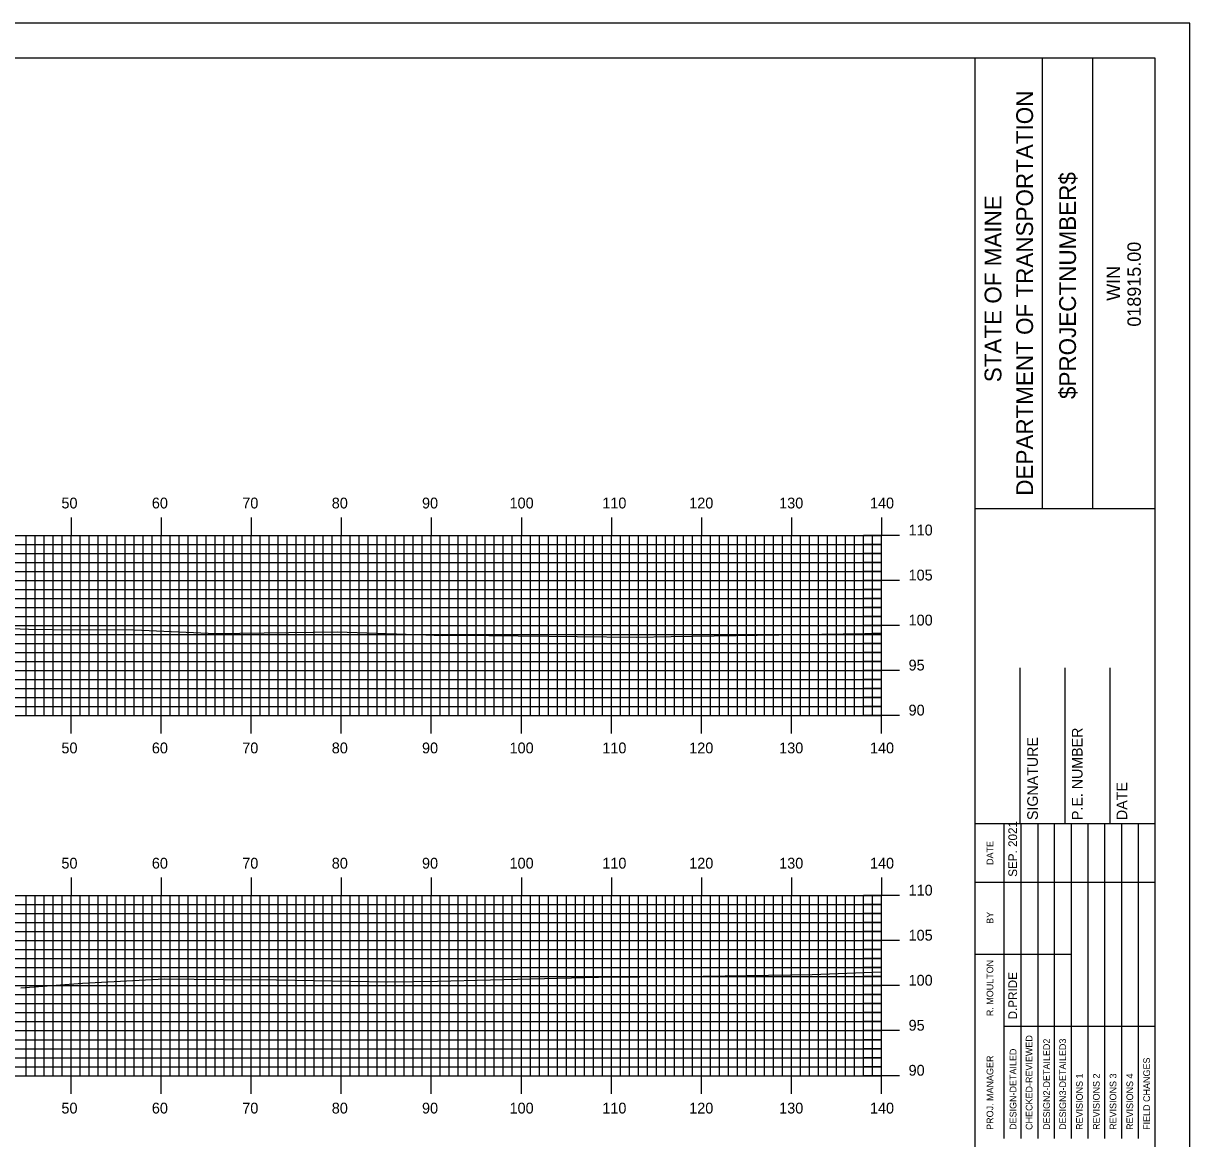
# Model space of a CAD drawing. Extents: x 1774383 to 1774727, y 442591 to 442811.
# Drawn here: x 1774593.9 to 1774723.4, y 442686.7 to 442810.5 of the extents above; entities that cross this region are included whole.
import ezdxf

# ---------------------------------------------------------------- set-up
doc = ezdxf.new("R2010")
doc.units = 0
for name, color, linetype in [('BORDER', 7, 'Continuous'), ('H_V ANNOTATION', 7, 'Continuous'), ('MAJOR', 7, 'Continuous'), ('MINOR', 7, 'Continuous'), ('PLOT BOUNDARY', 7, 'Continuous'), ('S_Roadway_Centerline', 7, 'Continuous')]:
    doc.layers.add(name, color=color, linetype=linetype)

msp = doc.modelspace()

# ---------------------------------------------------------------- linework, layer by layer
at = {"layer": 'BORDER'}
for p, q in [((1774699.57, 442596.67), (1774699.57, 442806.67)), ((1774707.03, 442756.66), (1774707.03, 442806.66)), ((1774712.62, 442756.66), (1774712.62, 442806.66)), ((1774699.57, 442756.65), (1774719.57, 442756.65)), ((1774704.57, 442721.67), (1774704.57, 442738.97)), ((1774709.57, 442721.67), (1774709.57, 442738.97)), ((1774714.57, 442721.67), (1774714.57, 442738.97)), ((1774699.57, 442721.67), (1774719.57, 442721.67))]:
    msp.add_line(p, q, dxfattribs=at)
msp.add_lwpolyline([(1774399.57, 442596.67), (1774719.57, 442596.67), (1774719.57, 442806.67), (1774399.57, 442806.67)], close=True, dxfattribs=at)
for points in [[(1774702.8, 442715.17), (1774702.8, 442721.67)], [(1774704.67, 442686.68), (1774704.67, 442721.67)], [(1774706.53, 442721.67), (1774706.53, 442686.68)], [(1774708.39, 442686.68), (1774708.39, 442721.67)], [(1774710.26, 442686.68), (1774710.26, 442721.67)], [(1774712.12, 442686.68), (1774712.12, 442721.67)], [(1774713.98, 442686.68), (1774713.98, 442721.67)], [(1774715.85, 442686.68), (1774715.85, 442721.67)], [(1774717.71, 442686.68), (1774717.71, 442721.67)], [(1774702.8, 442686.68), (1774702.8, 442720.26)], [(1774699.57, 442715.17), (1774719.57, 442715.17)], [(1774699.57, 442707.17), (1774702.8, 442707.17)], [(1774702.8, 442707.17), (1774710.26, 442707.17)], [(1774702.8, 442699.17), (1774719.57, 442699.17)]]:
    msp.add_lwpolyline(points, dxfattribs=at)
at = {"layer": 'MAJOR'}
for p, q in [((1774599.17, 442755.67), (1774599.17, 442753.67)), ((1774609.17, 442755.67), (1774609.17, 442753.67)), ((1774619.17, 442755.67), (1774619.17, 442753.67)), ((1774629.17, 442755.67), (1774629.17, 442753.67)), ((1774639.17, 442755.67), (1774639.17, 442753.67)), ((1774649.17, 442755.67), (1774649.17, 442753.67)), ((1774659.17, 442755.67), (1774659.17, 442753.67)), ((1774669.17, 442755.67), (1774669.17, 442753.67)), ((1774679.17, 442755.67), (1774679.17, 442753.67)), ((1774689.17, 442755.67), (1774689.17, 442753.67)), ((1774409.17, 442753.67), (1774689.17, 442753.67)), ((1774409.17, 442753.67), (1774689.17, 442753.67)), ((1774599.17, 442733.67), (1774599.17, 442753.67)), ((1774609.17, 442733.67), (1774609.17, 442753.67)), ((1774619.17, 442733.67), (1774619.17, 442753.67)), ((1774629.17, 442733.67), (1774629.17, 442753.67)), ((1774639.17, 442733.67), (1774639.17, 442753.67)), ((1774649.17, 442733.67), (1774649.17, 442753.67)), ((1774659.17, 442733.67), (1774659.17, 442753.67)), ((1774669.17, 442733.67), (1774669.17, 442753.67)), ((1774679.17, 442733.67), (1774679.17, 442753.67)), ((1774691.18, 442753.67), (1774687.17, 442753.67)), ((1774689.17, 442733.67), (1774689.17, 442753.67)), ((1774689.17, 442733.67), (1774689.17, 442753.67)), ((1774409.17, 442748.67), (1774689.17, 442748.67)), ((1774691.18, 442748.67), (1774687.17, 442748.67)), ((1774409.17, 442743.67), (1774689.17, 442743.67)), ((1774691.18, 442743.67), (1774687.17, 442743.67)), ((1774409.17, 442738.67), (1774689.17, 442738.67)), ((1774691.18, 442738.67), (1774687.17, 442738.67)), ((1774409.17, 442733.67), (1774689.17, 442733.67)), ((1774409.17, 442733.67), (1774689.17, 442733.67)), ((1774599.17, 442731.66), (1774599.17, 442733.67)), ((1774609.17, 442731.66), (1774609.17, 442733.67)), ((1774619.17, 442731.66), (1774619.17, 442733.67)), ((1774629.17, 442731.66), (1774629.17, 442733.67)), ((1774639.17, 442731.66), (1774639.17, 442733.67)), ((1774649.17, 442731.66), (1774649.17, 442733.67)), ((1774659.17, 442731.66), (1774659.17, 442733.67)), ((1774669.17, 442731.66), (1774669.17, 442733.67)), ((1774679.17, 442731.66), (1774679.17, 442733.67)), ((1774691.18, 442733.67), (1774687.17, 442733.67)), ((1774689.17, 442731.66), (1774689.17, 442733.67)), ((1774599.17, 442715.67), (1774599.17, 442713.67)), ((1774609.17, 442715.67), (1774609.17, 442713.67)), ((1774619.17, 442715.67), (1774619.17, 442713.67)), ((1774629.17, 442715.67), (1774629.17, 442713.67)), ((1774639.17, 442715.67), (1774639.17, 442713.67)), ((1774649.17, 442715.67), (1774649.17, 442713.67)), ((1774659.17, 442715.67), (1774659.17, 442713.67)), ((1774669.17, 442715.67), (1774669.17, 442713.67)), ((1774679.17, 442715.67), (1774679.17, 442713.67)), ((1774689.17, 442715.67), (1774689.17, 442713.67)), ((1774409.17, 442713.67), (1774689.17, 442713.67)), ((1774409.17, 442713.67), (1774689.17, 442713.67)), ((1774599.17, 442693.67), (1774599.17, 442713.67)), ((1774609.17, 442693.67), (1774609.17, 442713.67)), ((1774619.17, 442693.67), (1774619.17, 442713.67)), ((1774629.17, 442693.67), (1774629.17, 442713.67)), ((1774639.17, 442693.67), (1774639.17, 442713.67)), ((1774649.17, 442693.67), (1774649.17, 442713.67)), ((1774659.17, 442693.67), (1774659.17, 442713.67)), ((1774669.17, 442693.67), (1774669.17, 442713.67)), ((1774679.17, 442693.67), (1774679.17, 442713.67)), ((1774691.18, 442713.67), (1774687.17, 442713.67)), ((1774689.17, 442693.67), (1774689.17, 442713.67)), ((1774689.17, 442693.67), (1774689.17, 442713.67)), ((1774409.17, 442708.67), (1774689.17, 442708.67)), ((1774691.18, 442708.67), (1774687.17, 442708.67)), ((1774409.17, 442703.67), (1774689.17, 442703.67)), ((1774691.18, 442703.67), (1774687.17, 442703.67)), ((1774409.17, 442698.67), (1774689.17, 442698.67)), ((1774691.18, 442698.67), (1774687.17, 442698.67)), ((1774409.17, 442693.67), (1774689.17, 442693.67)), ((1774409.17, 442693.67), (1774689.17, 442693.67)), ((1774599.17, 442691.66), (1774599.17, 442693.67)), ((1774609.17, 442691.66), (1774609.17, 442693.67)), ((1774619.17, 442691.66), (1774619.17, 442693.67)), ((1774629.17, 442691.66), (1774629.17, 442693.67)), ((1774639.17, 442691.66), (1774639.17, 442693.67)), ((1774649.17, 442691.66), (1774649.17, 442693.67)), ((1774659.17, 442691.66), (1774659.17, 442693.67)), ((1774669.17, 442691.66), (1774669.17, 442693.67)), ((1774679.17, 442691.66), (1774679.17, 442693.67)), ((1774691.18, 442693.67), (1774687.17, 442693.67)), ((1774689.17, 442691.66), (1774689.17, 442693.67))]:
    msp.add_line(p, q, dxfattribs=at)
at = {"layer": 'MINOR'}
for p, q in [((1774594.17, 442733.67), (1774594.17, 442753.67)), ((1774595.17, 442733.67), (1774595.17, 442753.67)), ((1774596.17, 442733.67), (1774596.17, 442753.67)), ((1774597.17, 442733.67), (1774597.17, 442753.67)), ((1774598.17, 442733.67), (1774598.17, 442753.67)), ((1774600.17, 442733.67), (1774600.17, 442753.67)), ((1774601.17, 442733.67), (1774601.17, 442753.67)), ((1774602.17, 442733.67), (1774602.17, 442753.67)), ((1774603.17, 442733.67), (1774603.17, 442753.67)), ((1774604.17, 442733.67), (1774604.17, 442753.67)), ((1774605.17, 442733.67), (1774605.17, 442753.67)), ((1774606.17, 442733.67), (1774606.17, 442753.67)), ((1774607.17, 442733.67), (1774607.17, 442753.67)), ((1774608.17, 442733.67), (1774608.17, 442753.67)), ((1774610.17, 442733.67), (1774610.17, 442753.67)), ((1774611.17, 442733.67), (1774611.17, 442753.67)), ((1774612.17, 442733.67), (1774612.17, 442753.67)), ((1774613.17, 442733.67), (1774613.17, 442753.67)), ((1774614.17, 442733.67), (1774614.17, 442753.67)), ((1774615.17, 442733.67), (1774615.17, 442753.67)), ((1774616.17, 442733.67), (1774616.17, 442753.67)), ((1774617.17, 442733.67), (1774617.17, 442753.67)), ((1774618.17, 442733.67), (1774618.17, 442753.67)), ((1774620.17, 442733.67), (1774620.17, 442753.67)), ((1774621.17, 442733.67), (1774621.17, 442753.67)), ((1774622.17, 442733.67), (1774622.17, 442753.67)), ((1774623.17, 442733.67), (1774623.17, 442753.67)), ((1774624.17, 442733.67), (1774624.17, 442753.67)), ((1774625.17, 442733.67), (1774625.17, 442753.67)), ((1774626.17, 442733.67), (1774626.17, 442753.67)), ((1774627.17, 442733.67), (1774627.17, 442753.67)), ((1774628.17, 442733.67), (1774628.17, 442753.67)), ((1774630.17, 442733.67), (1774630.17, 442753.67)), ((1774631.17, 442733.67), (1774631.17, 442753.67)), ((1774632.17, 442733.67), (1774632.17, 442753.67)), ((1774633.17, 442733.67), (1774633.17, 442753.67)), ((1774634.17, 442733.67), (1774634.17, 442753.67)), ((1774635.17, 442733.67), (1774635.17, 442753.67)), ((1774636.17, 442733.67), (1774636.17, 442753.67)), ((1774637.17, 442733.67), (1774637.17, 442753.67)), ((1774638.17, 442733.67), (1774638.17, 442753.67)), ((1774640.17, 442733.67), (1774640.17, 442753.67)), ((1774641.17, 442733.67), (1774641.17, 442753.67)), ((1774642.17, 442733.67), (1774642.17, 442753.67)), ((1774643.17, 442733.67), (1774643.17, 442753.67)), ((1774644.17, 442733.67), (1774644.17, 442753.67)), ((1774645.17, 442733.67), (1774645.17, 442753.67)), ((1774646.17, 442733.67), (1774646.17, 442753.67)), ((1774647.17, 442733.67), (1774647.17, 442753.67)), ((1774648.17, 442733.67), (1774648.17, 442753.67)), ((1774650.17, 442733.67), (1774650.17, 442753.67)), ((1774651.17, 442733.67), (1774651.17, 442753.67)), ((1774652.17, 442733.67), (1774652.17, 442753.67)), ((1774653.17, 442733.67), (1774653.17, 442753.67)), ((1774654.17, 442733.67), (1774654.17, 442753.67)), ((1774655.17, 442733.67), (1774655.17, 442753.67)), ((1774656.17, 442733.67), (1774656.17, 442753.67)), ((1774657.17, 442733.67), (1774657.17, 442753.67)), ((1774658.17, 442733.67), (1774658.17, 442753.67)), ((1774660.17, 442733.67), (1774660.17, 442753.67)), ((1774661.17, 442733.67), (1774661.17, 442753.67)), ((1774662.17, 442733.67), (1774662.17, 442753.67)), ((1774663.17, 442733.67), (1774663.17, 442753.67)), ((1774664.17, 442733.67), (1774664.17, 442753.67)), ((1774665.17, 442733.67), (1774665.17, 442753.67)), ((1774666.17, 442733.67), (1774666.17, 442753.67)), ((1774667.17, 442733.67), (1774667.17, 442753.67)), ((1774668.17, 442733.67), (1774668.17, 442753.67)), ((1774670.17, 442733.67), (1774670.17, 442753.67)), ((1774671.17, 442733.67), (1774671.17, 442753.67)), ((1774672.17, 442733.67), (1774672.17, 442753.67)), ((1774673.17, 442733.67), (1774673.17, 442753.67)), ((1774674.17, 442733.67), (1774674.17, 442753.67)), ((1774675.17, 442733.67), (1774675.17, 442753.67)), ((1774676.17, 442733.67), (1774676.17, 442753.67)), ((1774677.17, 442733.67), (1774677.17, 442753.67)), ((1774678.17, 442733.67), (1774678.17, 442753.67)), ((1774680.17, 442733.67), (1774680.17, 442753.67)), ((1774681.17, 442733.67), (1774681.17, 442753.67)), ((1774682.17, 442733.67), (1774682.17, 442753.67)), ((1774683.17, 442733.67), (1774683.17, 442753.67)), ((1774684.17, 442733.67), (1774684.17, 442753.67)), ((1774685.17, 442733.67), (1774685.17, 442753.67)), ((1774686.17, 442733.67), (1774686.17, 442753.67)), ((1774687.17, 442733.67), (1774687.17, 442753.67)), ((1774688.17, 442733.67), (1774688.17, 442753.67)), ((1774409.17, 442752.67), (1774689.17, 442752.67)), ((1774689.17, 442752.67), (1774687.17, 442752.67)), ((1774409.17, 442751.67), (1774689.17, 442751.67)), ((1774409.17, 442750.67), (1774689.17, 442750.67)), ((1774689.17, 442751.67), (1774687.17, 442751.67)), ((1774689.17, 442750.67), (1774687.17, 442750.67)), ((1774409.17, 442749.67), (1774689.17, 442749.67)), ((1774689.17, 442749.67), (1774687.17, 442749.67)), ((1774409.17, 442747.67), (1774689.17, 442747.67)), ((1774689.17, 442747.67), (1774687.17, 442747.67)), ((1774409.17, 442746.67), (1774689.17, 442746.67)), ((1774409.17, 442745.67), (1774689.17, 442745.67)), ((1774689.17, 442746.67), (1774687.17, 442746.67)), ((1774689.17, 442745.67), (1774687.17, 442745.67)), ((1774409.17, 442744.67), (1774689.17, 442744.67)), ((1774689.17, 442744.67), (1774687.17, 442744.67)), ((1774409.17, 442742.67), (1774689.17, 442742.67)), ((1774409.17, 442741.67), (1774689.17, 442741.67)), ((1774689.17, 442742.67), (1774687.17, 442742.67)), ((1774689.17, 442741.67), (1774687.17, 442741.67)), ((1774409.17, 442740.67), (1774689.17, 442740.67)), ((1774689.17, 442740.67), (1774687.17, 442740.67)), ((1774409.17, 442739.67), (1774689.17, 442739.67)), ((1774689.17, 442739.67), (1774687.17, 442739.67)), ((1774409.17, 442737.67), (1774689.17, 442737.67)), ((1774409.17, 442736.67), (1774689.17, 442736.67)), ((1774689.17, 442737.67), (1774687.17, 442737.67)), ((1774689.17, 442736.67), (1774687.17, 442736.67)), ((1774409.17, 442735.67), (1774689.17, 442735.67)), ((1774689.17, 442735.67), (1774687.17, 442735.67)), ((1774409.17, 442734.67), (1774689.17, 442734.67)), ((1774689.17, 442734.67), (1774687.17, 442734.67)), ((1774594.17, 442693.67), (1774594.17, 442713.67)), ((1774595.17, 442693.67), (1774595.17, 442713.67)), ((1774596.17, 442693.67), (1774596.17, 442713.67)), ((1774597.17, 442693.67), (1774597.17, 442713.67)), ((1774598.17, 442693.67), (1774598.17, 442713.67)), ((1774600.17, 442693.67), (1774600.17, 442713.67)), ((1774601.17, 442693.67), (1774601.17, 442713.67)), ((1774602.17, 442693.67), (1774602.17, 442713.67)), ((1774603.17, 442693.67), (1774603.17, 442713.67)), ((1774604.17, 442693.67), (1774604.17, 442713.67)), ((1774605.17, 442693.67), (1774605.17, 442713.67)), ((1774606.17, 442693.67), (1774606.17, 442713.67)), ((1774607.17, 442693.67), (1774607.17, 442713.67)), ((1774608.17, 442693.67), (1774608.17, 442713.67)), ((1774610.17, 442693.67), (1774610.17, 442713.67)), ((1774611.17, 442693.67), (1774611.17, 442713.67)), ((1774612.17, 442693.67), (1774612.17, 442713.67)), ((1774613.17, 442693.67), (1774613.17, 442713.67)), ((1774614.17, 442693.67), (1774614.17, 442713.67)), ((1774615.17, 442693.67), (1774615.17, 442713.67)), ((1774616.17, 442693.67), (1774616.17, 442713.67)), ((1774617.17, 442693.67), (1774617.17, 442713.67)), ((1774618.17, 442693.67), (1774618.17, 442713.67)), ((1774620.17, 442693.67), (1774620.17, 442713.67)), ((1774621.17, 442693.67), (1774621.17, 442713.67)), ((1774622.17, 442693.67), (1774622.17, 442713.67)), ((1774623.17, 442693.67), (1774623.17, 442713.67)), ((1774624.17, 442693.67), (1774624.17, 442713.67)), ((1774625.17, 442693.67), (1774625.17, 442713.67)), ((1774626.17, 442693.67), (1774626.17, 442713.67)), ((1774627.17, 442693.67), (1774627.17, 442713.67)), ((1774628.17, 442693.67), (1774628.17, 442713.67)), ((1774630.17, 442693.67), (1774630.17, 442713.67)), ((1774631.17, 442693.67), (1774631.17, 442713.67)), ((1774632.17, 442693.67), (1774632.17, 442713.67)), ((1774633.17, 442693.67), (1774633.17, 442713.67)), ((1774634.17, 442693.67), (1774634.17, 442713.67)), ((1774635.17, 442693.67), (1774635.17, 442713.67)), ((1774636.17, 442693.67), (1774636.17, 442713.67)), ((1774637.17, 442693.67), (1774637.17, 442713.67)), ((1774638.17, 442693.67), (1774638.17, 442713.67)), ((1774640.17, 442693.67), (1774640.17, 442713.67)), ((1774641.17, 442693.67), (1774641.17, 442713.67)), ((1774642.17, 442693.67), (1774642.17, 442713.67)), ((1774643.17, 442693.67), (1774643.17, 442713.67)), ((1774644.17, 442693.67), (1774644.17, 442713.67)), ((1774645.17, 442693.67), (1774645.17, 442713.67)), ((1774646.17, 442693.67), (1774646.17, 442713.67)), ((1774647.17, 442693.67), (1774647.17, 442713.67)), ((1774648.17, 442693.67), (1774648.17, 442713.67)), ((1774650.17, 442693.67), (1774650.17, 442713.67)), ((1774651.17, 442693.67), (1774651.17, 442713.67)), ((1774652.17, 442693.67), (1774652.17, 442713.67)), ((1774653.17, 442693.67), (1774653.17, 442713.67)), ((1774654.17, 442693.67), (1774654.17, 442713.67)), ((1774655.17, 442693.67), (1774655.17, 442713.67)), ((1774656.17, 442693.67), (1774656.17, 442713.67)), ((1774657.17, 442693.67), (1774657.17, 442713.67)), ((1774658.17, 442693.67), (1774658.17, 442713.67)), ((1774660.17, 442693.67), (1774660.17, 442713.67)), ((1774661.17, 442693.67), (1774661.17, 442713.67)), ((1774662.17, 442693.67), (1774662.17, 442713.67)), ((1774663.17, 442693.67), (1774663.17, 442713.67)), ((1774664.17, 442693.67), (1774664.17, 442713.67)), ((1774665.17, 442693.67), (1774665.17, 442713.67)), ((1774666.17, 442693.67), (1774666.17, 442713.67)), ((1774667.17, 442693.67), (1774667.17, 442713.67)), ((1774668.17, 442693.67), (1774668.17, 442713.67)), ((1774670.17, 442693.67), (1774670.17, 442713.67)), ((1774671.17, 442693.67), (1774671.17, 442713.67)), ((1774672.17, 442693.67), (1774672.17, 442713.67)), ((1774673.17, 442693.67), (1774673.17, 442713.67)), ((1774674.17, 442693.67), (1774674.17, 442713.67)), ((1774675.17, 442693.67), (1774675.17, 442713.67)), ((1774676.17, 442693.67), (1774676.17, 442713.67)), ((1774677.17, 442693.67), (1774677.17, 442713.67)), ((1774678.17, 442693.67), (1774678.17, 442713.67)), ((1774680.17, 442693.67), (1774680.17, 442713.67)), ((1774681.17, 442693.67), (1774681.17, 442713.67)), ((1774682.17, 442693.67), (1774682.17, 442713.67)), ((1774683.17, 442693.67), (1774683.17, 442713.67)), ((1774684.17, 442693.67), (1774684.17, 442713.67)), ((1774685.17, 442693.67), (1774685.17, 442713.67)), ((1774686.17, 442693.67), (1774686.17, 442713.67)), ((1774687.17, 442693.67), (1774687.17, 442713.67)), ((1774688.17, 442693.67), (1774688.17, 442713.67)), ((1774409.17, 442712.67), (1774689.17, 442712.67)), ((1774689.17, 442712.67), (1774687.17, 442712.67)), ((1774409.17, 442711.67), (1774689.17, 442711.67)), ((1774409.17, 442710.67), (1774689.17, 442710.67)), ((1774689.17, 442711.67), (1774687.17, 442711.67)), ((1774689.17, 442710.67), (1774687.17, 442710.67)), ((1774409.17, 442709.67), (1774689.17, 442709.67)), ((1774689.17, 442709.67), (1774687.17, 442709.67)), ((1774409.17, 442707.67), (1774689.17, 442707.67)), ((1774409.17, 442706.67), (1774689.17, 442706.67)), ((1774689.17, 442707.67), (1774687.17, 442707.67)), ((1774689.17, 442706.67), (1774687.17, 442706.67)), ((1774409.17, 442705.67), (1774689.17, 442705.67)), ((1774689.17, 442705.67), (1774687.17, 442705.67)), ((1774409.17, 442704.67), (1774689.17, 442704.67)), ((1774689.17, 442704.67), (1774687.17, 442704.67)), ((1774409.17, 442702.67), (1774689.17, 442702.67)), ((1774409.17, 442701.67), (1774689.17, 442701.67)), ((1774689.17, 442702.67), (1774687.17, 442702.67)), ((1774689.17, 442701.67), (1774687.17, 442701.67)), ((1774409.17, 442700.67), (1774689.17, 442700.67)), ((1774689.17, 442700.67), (1774687.17, 442700.67)), ((1774409.17, 442699.67), (1774689.17, 442699.67)), ((1774689.17, 442699.67), (1774687.17, 442699.67)), ((1774409.17, 442697.67), (1774689.17, 442697.67)), ((1774689.17, 442697.67), (1774687.17, 442697.67)), ((1774409.17, 442696.67), (1774689.17, 442696.67)), ((1774689.17, 442696.67), (1774687.17, 442696.67)), ((1774409.17, 442695.67), (1774689.17, 442695.67)), ((1774689.17, 442695.67), (1774687.17, 442695.67)), ((1774409.17, 442694.67), (1774689.17, 442694.67)), ((1774689.17, 442694.67), (1774687.17, 442694.67))]:
    msp.add_line(p, q, dxfattribs=at)
at = {"layer": 'PLOT BOUNDARY'}
msp.add_lwpolyline([(1774383.39, 442590.55), (1774723.39, 442590.55), (1774723.39, 442810.55), (1774383.39, 442810.55)], close=True, dxfattribs=at)
at = {"layer": 'S_Roadway_Centerline'}
for points in [[(1774591.67, 442743.36), (1774594.43, 442743.27), (1774597.2, 442743.23), (1774606.23, 442743.19), (1774615.21, 442742.79), (1774628.77, 442742.97), (1774638.56, 442742.65), (1774640.4, 442742.56), (1774642.27, 442742.58), (1774661.92, 442742.37), (1774665.8, 442742.46), (1774687.31, 442742.79), (1774688.09, 442742.81), (1774689.17, 442742.86)], [(1774593.58, 442703.42), (1774600.43, 442703.94), (1774609.56, 442704.41), (1774616.13, 442704.36), (1774621.97, 442704.3), (1774634.29, 442704.09), (1774639.85, 442704.18), (1774645.75, 442704.32), (1774657.73, 442704.6), (1774666.95, 442704.69), (1774681.45, 442704.89), (1774689.17, 442705.19)]]:
    msp.add_lwpolyline(points, dxfattribs=at)

# ---------------------------------------------------------------- texts
at = {"layer": 'BORDER'}
for s, height, p in [('DEPARTMENT OF TRANSPORTATION', 1.8635, (1774705.99, 442758.08)), ('$PROJECTNUMBER$', 1.8635, (1774710.76, 442768.82)), ('STATE OF MAINE', 1.8635, (1774702.48, 442770.69)), ('018915.00', 1.491, (1774717.96, 442776.86)), ('WIN', 1.491, (1774715.65, 442779.73)), ('P.E. NUMBER', 1.1811, (1774711.49, 442722.06)), ('SIGNATURE', 1.181, (1774706.53, 442722.06)), ('DATE', 1.181, (1774716.45, 442722.06)), ('SEP. 2021', 0.969, (1774704.22, 442715.76)), ('DATE', 0.743, (1774701.58, 442717.08)), ('BY', 0.743, (1774701.58, 442710.54)), ('R. MOULTON', 0.745, (1774701.58, 442700.28)), ('D.PRIDE', 0.969, (1774704.22, 442699.92)), ('CHECKED-REVIEWED', 0.7455, (1774705.93, 442687.65)), ('DESIGN2-DETAILED2', 0.7455, (1774707.87, 442687.65)), ('DESIGN3-DETAILED3', 0.7455, (1774709.66, 442687.65)), ('DESIGN-DETAILED', 0.7455, (1774704.15, 442687.65)), ('PROJ. MANAGER', 0.7455, (1774701.58, 442687.65)), ('FIELD CHANGES', 0.7455, (1774718.98, 442687.65)), ('REVISIONS 1', 0.7455, (1774711.52, 442687.65)), ('REVISIONS 2', 0.7455, (1774713.39, 442687.65)), ('REVISIONS 3', 0.7455, (1774715.25, 442687.65)), ('REVISIONS 4', 0.7455, (1774717.11, 442687.65))]:
    msp.add_text(s, height=height, rotation=90, dxfattribs=at).set_placement(p)
at = {"layer": 'H_V ANNOTATION'}
for s, p in [('50', (1774598.1, 442756.67)), ('60', (1774608.14, 442756.67)), ('70', (1774618.18, 442756.67)), ('80', (1774628.12, 442756.67)), ('90', (1774638.14, 442756.67)), ('100', (1774647.86, 442756.67)), ('110', (1774658.16, 442756.67)), ('120', (1774667.81, 442756.67)), ('130', (1774677.8, 442756.67)), ('140', (1774687.88, 442756.67)), ('110', (1774692.17, 442753.67)), ('105', (1774692.17, 442748.67)), ('100', (1774692.17, 442743.67)), ('95', (1774692.17, 442738.67)), ('90', (1774692.17, 442733.67)), ('50', (1774598.1, 442729.47)), ('60', (1774608.14, 442729.47)), ('70', (1774618.18, 442729.47)), ('80', (1774628.12, 442729.47)), ('90', (1774638.14, 442729.47)), ('100', (1774647.86, 442729.47)), ('110', (1774658.16, 442729.47)), ('120', (1774667.81, 442729.47)), ('130', (1774677.8, 442729.47)), ('140', (1774687.88, 442729.47)), ('50', (1774598.1, 442716.67)), ('60', (1774608.14, 442716.67)), ('70', (1774618.18, 442716.67)), ('80', (1774628.12, 442716.67)), ('90', (1774638.14, 442716.67)), ('100', (1774647.86, 442716.67)), ('110', (1774658.16, 442716.67)), ('120', (1774667.81, 442716.67)), ('130', (1774677.8, 442716.67)), ('140', (1774687.88, 442716.67)), ('110', (1774692.17, 442713.67)), ('105', (1774692.17, 442708.67)), ('100', (1774692.17, 442703.67)), ('95', (1774692.17, 442698.67)), ('90', (1774692.17, 442693.67)), ('50', (1774598.1, 442689.47)), ('60', (1774608.14, 442689.47)), ('70', (1774618.18, 442689.47)), ('80', (1774628.12, 442689.47)), ('90', (1774638.14, 442689.47)), ('100', (1774647.86, 442689.47)), ('110', (1774658.16, 442689.47)), ('120', (1774667.81, 442689.47)), ('130', (1774677.8, 442689.47)), ('140', (1774687.88, 442689.47))]:
    msp.add_text(s, height=1.2, dxfattribs=at).set_placement(p)

doc.saveas('drawing.dxf')
